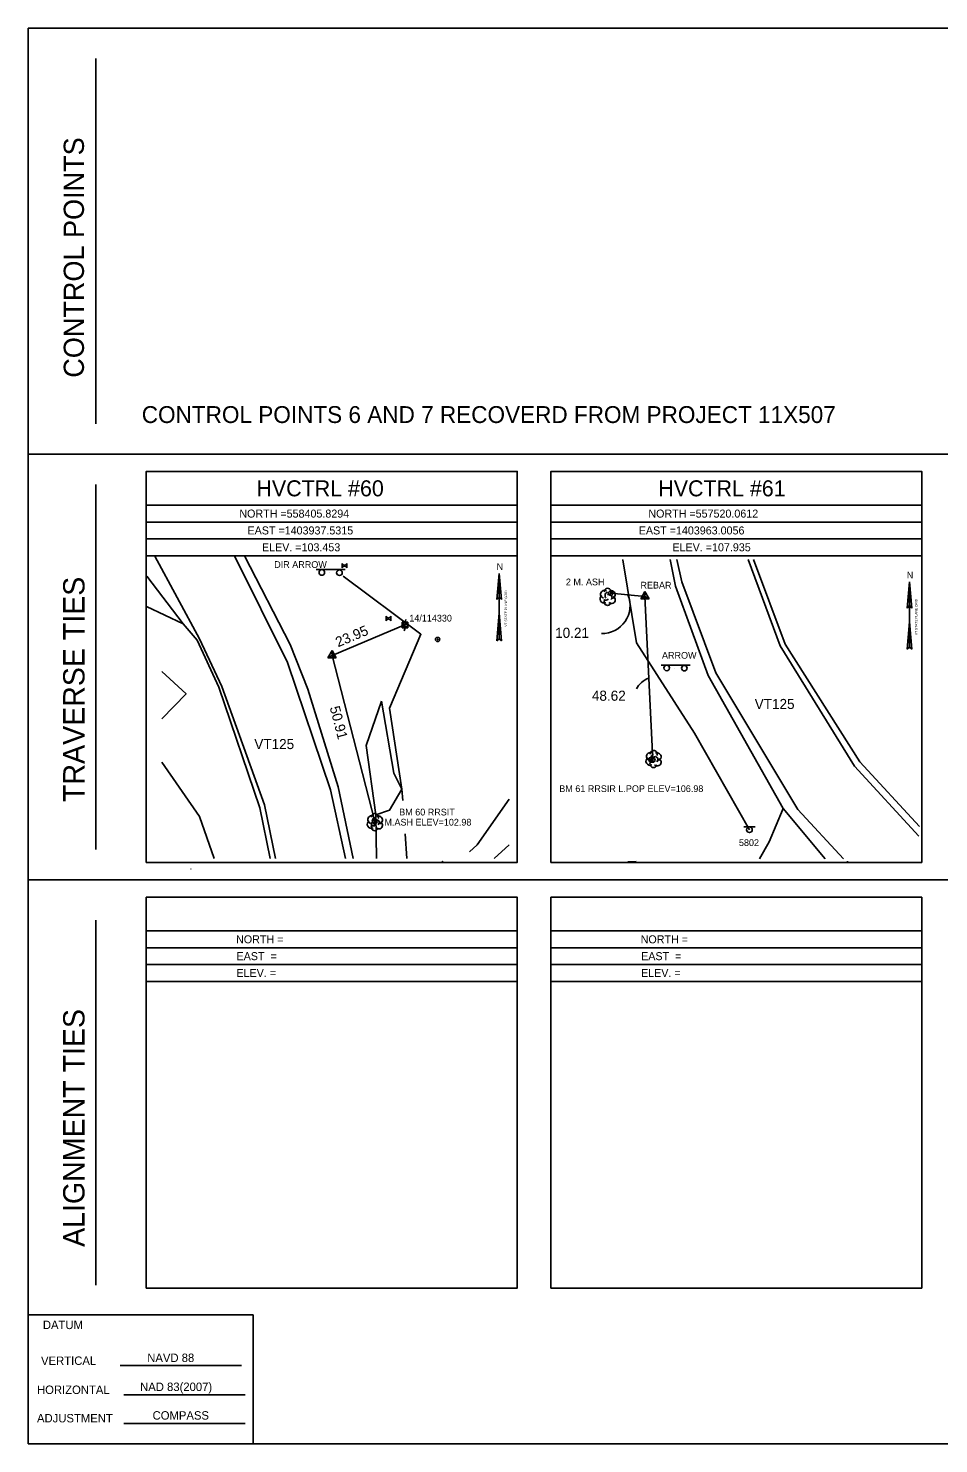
# Model space of a CAD drawing. Extents: x 1514039 to 1514679, y 870735 to 871155.
# Drawn here: x 1514038.6 to 1514308.6, y 870735.2 to 871155.2 of the extents above; entities that cross this region are included whole.
import ezdxf

# ---------------------------------------------------------------- set-up
doc = ezdxf.new("R2010")
doc.units = 0
for name, color, linetype in [('C_A', 7, 'Continuous'), ('C_C', 7, 'Continuous'), ('CBP', 7, 'Continuous'), ('CPBM', 7, 'Continuous'), ('CPSM', 7, 'Continuous'), ('Default', 7, 'Continuous'), ('L_C', 7, 'Continuous'), ('LASF', 7, 'Continuous'), ('LAWA', 7, 'Continuous'), ('LAWE', 7, 'Continuous'), ('LELB', 7, 'Continuous'), ('LSOGT', 7, 'Continuous'), ('LTD', 7, 'Continuous'), ('NBL1', 7, 'Continuous'), ('NBL2', 7, 'Continuous'), ('NNA_P', 7, 'Continuous'), ('PET', 7, 'Continuous'), ('PSP', 7, 'Continuous'), ('R_TIC', 7, 'Continuous'), ('RDG', 7, 'Continuous'), ('RDP', 7, 'Continuous'), ('S_C', 7, 'Continuous'), ('SSGN', 7, 'Continuous'), ('U_C', 7, 'Continuous'), ('UP', 7, 'Continuous'), ('UPGW', 7, 'Continuous'), ('UWV', 7, 'Continuous')]:
    doc.layers.add(name, color=color, linetype=linetype)

msp = doc.modelspace()

# ---------------------------------------------------------------- linework, layer by layer
at = {"layer": 'CBP'}
for centre, radius in [((1514211.27, 870987.54), 0.625), ((1514211.27, 870987.54), 0.0833), ((1514150.45, 870978.27), 0.625), ((1514150.45, 870978.27), 0.0833), ((1514223.82, 870938.08), 0.625), ((1514223.82, 870938.08), 0.0833), ((1514141.37, 870919.82), 0.625), ((1514141.37, 870919.82), 0.0833)]:
    msp.add_circle(centre, radius, dxfattribs=at)
at = {"layer": 'CPBM'}
for p, q in [((1514222.66, 870937.7), (1514222.66, 870938.7)), ((1514222.66, 870938.7), (1514223.66, 870938.7)), ((1514223.66, 870937.7), (1514222.66, 870937.7)), ((1514223.16, 870938.2), (1514223.16, 870938.2)), ((1514223.16, 870938.2), (1514223.16, 870938.2)), ((1514223.66, 870938.7), (1514223.66, 870937.7)), ((1514140.35, 870918.59), (1514140.35, 870919.59)), ((1514140.35, 870919.59), (1514141.35, 870919.59)), ((1514141.35, 870918.59), (1514140.35, 870918.59)), ((1514140.85, 870919.09), (1514140.85, 870919.09)), ((1514140.85, 870919.09), (1514140.85, 870919.09)), ((1514141.35, 870919.59), (1514141.35, 870918.59))]:
    msp.add_line(p, q, dxfattribs=at)
at = {"layer": 'CPSM'}
for p, q in [((1514220.19, 870985.92), (1514221.44, 870988.08)), ((1514222.69, 870985.92), (1514221.44, 870988.08)), ((1514221.44, 870986.64), (1514221.44, 870988.08)), ((1514220.19, 870985.92), (1514221.44, 870986.64)), ((1514220.19, 870985.92), (1514222.69, 870985.92)), ((1514221.44, 870986.64), (1514221.44, 870986.64)), ((1514221.44, 870986.64), (1514222.69, 870985.92)), ((1514127.39, 870968.4), (1514128.64, 870970.56)), ((1514127.39, 870968.4), (1514128.64, 870969.12)), ((1514127.39, 870968.4), (1514129.89, 870968.4)), ((1514129.89, 870968.4), (1514128.64, 870970.56)), ((1514128.64, 870969.12), (1514128.64, 870970.56)), ((1514128.64, 870969.12), (1514128.64, 870969.12)), ((1514128.64, 870969.12), (1514129.89, 870968.4))]:
    msp.add_line(p, q, dxfattribs=at)
at = {"layer": 'Default'}
for points in [[(1514211.37, 870987.57), (1514221.44, 870986.64), (1514223.82, 870938.08)], [(1514150.45, 870978.27), (1514128.64, 870969.12), (1514141.37, 870919.82)]]:
    msp.add_lwpolyline(points, dxfattribs=at)
for centre, radius, start, end in [((1514208.74, 870983.93), 8.3, 268.6041, 22.529), ((1514224.57, 870956.36), 6.31, 107.8692, 153.5783)]:
    msp.add_arc(centre, radius, start, end, dxfattribs=at)
at = {"layer": 'LASF'}
for points in [[(1514143.32, 870955.51), (1514138.75, 870942.45), (1514141.63, 870921.82)], [(1514143.32, 870955.51), (1514146.98, 870934.17), (1514149.38, 870929.42), (1514149.61, 870926.12)], [(1514150.33, 870916.14), (1514150.85, 870908.88)]]:
    msp.add_lwpolyline(points, dxfattribs=at)
at = {"layer": 'LAWA'}
for points in [[(1514252.42, 870917.39), (1514236.11, 870946.04), (1514218.99, 870972.84), (1514214.86, 870997.45), (1514214.84, 870997.56)], [(1514131.92, 870992.64), (1514155.03, 870975.42), (1514145.66, 870953.51), (1514149.38, 870929.42), (1514145.72, 870923.2), (1514141.63, 870921.82), (1514141.86, 870908.88)], [(1514078.16, 870964.37), (1514085.34, 870957.7), (1514078.16, 870950.36)], [(1514078.16, 870937.5), (1514089.32, 870921.35), (1514093.69, 870908.88)]]:
    msp.add_lwpolyline(points, dxfattribs=at)
at = {"layer": 'LAWE'}
msp.add_lwpolyline([(1514181.21, 870926.52), (1514171.74, 870912.92), (1514169.38, 870910.86)], dxfattribs=at)
at = {"layer": 'LELB'}
msp.add_lwpolyline([(1514181.21, 870912.94), (1514176.72, 870908.88)], dxfattribs=at)
at = {"layer": 'LSOGT'}
for p, q in [((1514161.42, 870907.99), (1514161.44, 870908.03)), ((1514161.48, 870907.99), (1514161.42, 870907.99)), ((1514161.44, 870908.03), (1514161.48, 870907.99)), ((1514281.5, 870908.03), (1514281.49, 870908.01)), ((1514281.49, 870908.01), (1514281.53, 870908.01)), ((1514281.56, 870908.01), (1514281.5, 870908.03)), ((1514281.5, 870908.03), (1514281.53, 870908.01)), ((1514281.53, 870908.01), (1514281.5, 870908.03)), ((1514281.53, 870908.01), (1514281.56, 870908.01))]:
    msp.add_line(p, q, dxfattribs=at)
at = {"layer": 'LTD'}
for p, q in [((1514210.37, 870986.57), (1514210.37, 870986.57)), ((1514210.37, 870986.57), (1514210.37, 870986.57)), ((1514223.98, 870938.44), (1514223.98, 870938.44)), ((1514223.98, 870938.44), (1514223.98, 870938.44)), ((1514141.33, 870919.69), (1514141.33, 870919.69)), ((1514141.33, 870919.69), (1514141.33, 870919.69))]:
    msp.add_line(p, q, dxfattribs=at)
for centre in [(1514210.42, 870988), (1514224.03, 870939.87), (1514141.38, 870921.13)]:
    msp.add_arc(centre, 1.05, 335.5272, 180.9563, dxfattribs=at)
for centre, major_axis, ratio, start_param, end_param in [((1514209.58, 870987.24), (1.21, -0.51), 0.895232, 1.570796, 4.712389), ((1514210.16, 870987.03), (-0.208, -0.792), 0.645439, 3.141593, 6.283185), ((1514211.41, 870987.15), (-1.14, -0.48), 0.949671, 1.570796, 4.712389), ((1514209.29, 870985.86), (0.58, -1.04), 0.959034, 3.141593, 6.283185), ((1514210.37, 870985.07), (0.26, 1.06), 0.942809, 1.570796, 4.712389), ((1514209.91, 870985.82), (-0.625, -0.083), 0.423636, 0, 3.141593), ((1514210.87, 870986.4), (-0.5, 0.667), 0.989748, 3.141593, 6.283185), ((1514211.37, 870985.74), (-1.09, 0.79), 0.841452, 1.570796, 4.712389), ((1514222.9, 870937.73), (0.58, -1.04), 0.959034, 3.141593, 6.283185), ((1514223.19, 870939.1), (1.21, -0.51), 0.895232, 1.570796, 4.712389), ((1514223.52, 870937.69), (-0.625, -0.083), 0.423636, 0, 3.141593), ((1514223.77, 870938.9), (-0.208, -0.792), 0.645439, 3.141593, 6.283185), ((1514224.48, 870938.27), (-0.5, 0.667), 0.989748, 3.141593, 6.283185), ((1514224.98, 870937.6), (-1.09, 0.79), 0.841452, 1.570796, 4.712389), ((1514225.02, 870939.02), (-1.14, -0.48), 0.949671, 1.570796, 4.712389), ((1514223.98, 870936.94), (0.26, 1.06), 0.942809, 1.570796, 4.712389), ((1514140.54, 870920.36), (1.21, -0.51), 0.895232, 1.570796, 4.712389), ((1514141.12, 870920.15), (-0.208, -0.792), 0.645439, 3.141593, 6.283185), ((1514141.83, 870919.53), (-0.5, 0.667), 0.989748, 3.141593, 6.283185), ((1514142.37, 870920.28), (-1.14, -0.48), 0.949671, 1.570796, 4.712389), ((1514140.25, 870918.98), (0.58, -1.04), 0.959034, 3.141593, 6.283185), ((1514141.33, 870918.19), (0.26, 1.06), 0.942809, 1.570796, 4.712389), ((1514140.87, 870918.94), (-0.625, -0.083), 0.423636, 0, 3.141593), ((1514142.33, 870918.86), (-1.09, 0.79), 0.841452, 1.570796, 4.712389)]:
    msp.add_ellipse(centre, major_axis=major_axis, ratio=ratio, start_param=start_param, end_param=end_param, dxfattribs=at)
at = {"layer": 'NBL1'}
msp.add_lwpolyline([(1514038.57, 870735.22), (1514678.57, 870735.22), (1514678.57, 871155.22), (1514038.57, 871155.22)], close=True, dxfattribs=at)
at = {"layer": 'NBL2'}
for p, q in [((1514058.57, 871037.89), (1514058.57, 871146.22)), ((1514038.57, 871028.89), (1514678.57, 871028.89)), ((1514058.57, 870911.55), (1514058.57, 871019.89)), ((1514183.57, 871013.72), (1514073.57, 871013.72)), ((1514303.57, 871013.72), (1514193.57, 871013.72)), ((1514183.57, 871008.72), (1514073.57, 871008.72)), ((1514303.57, 871008.72), (1514193.57, 871008.72)), ((1514183.57, 871003.72), (1514073.57, 871003.72)), ((1514303.57, 871003.72), (1514193.57, 871003.72)), ((1514183.57, 870998.72), (1514073.57, 870998.72)), ((1514197.6, 870998.72), (1514193.57, 870998.72)), ((1514300.42, 870998.72), (1514197.6, 870998.72)), ((1514303.57, 870998.72), (1514300.42, 870998.72)), ((1514038.57, 870902.55), (1514678.57, 870902.55)), ((1514058.57, 870782.22), (1514058.57, 870890.55)), ((1514183.57, 870887.39), (1514073.57, 870887.39)), ((1514303.57, 870887.39), (1514193.57, 870887.39)), ((1514183.57, 870882.39), (1514073.57, 870882.39)), ((1514303.57, 870882.39), (1514193.57, 870882.39)), ((1514183.57, 870877.39), (1514073.57, 870877.39)), ((1514303.57, 870877.39), (1514193.57, 870877.39)), ((1514183.57, 870872.39), (1514073.57, 870872.39)), ((1514303.57, 870872.39), (1514193.57, 870872.39)), ((1514105.24, 870773.47), (1514038.57, 870773.47)), ((1514105.24, 870773.47), (1514105.24, 870735.22)), ((1514105.24, 870773.47), (1514105.24, 870735.22)), ((1514065.81, 870758.45), (1514101.81, 870758.42)), ((1514066.92, 870749.67), (1514102.92, 870749.67)), ((1514066.92, 870741.24), (1514102.92, 870741.21))]:
    msp.add_line(p, q, dxfattribs=at)
for points in [[(1514073.57, 870907.72), (1514183.57, 870907.72), (1514183.57, 871023.72), (1514073.57, 871023.72)], [(1514193.57, 870907.72), (1514303.57, 870907.72), (1514303.57, 871023.72), (1514193.57, 871023.72)], [(1514073.57, 870781.39), (1514183.57, 870781.39), (1514183.57, 870897.39), (1514073.57, 870897.39)], [(1514193.57, 870781.39), (1514303.57, 870781.39), (1514303.57, 870897.39), (1514193.57, 870897.39)]]:
    msp.add_lwpolyline(points, close=True, dxfattribs=at)
at = {"layer": 'NNA_P'}
for p, q in [((1514177.55, 870985.68), (1514178.24, 870993.47)), ((1514178.24, 870974.1), (1514178.24, 870993.47)), ((1514178.93, 870985.68), (1514178.24, 870993.47)), ((1514299.21, 870983.17), (1514299.9, 870990.96)), ((1514299.91, 870971.59), (1514299.9, 870990.96)), ((1514300.6, 870983.17), (1514299.9, 870990.96)), ((1514177.55, 870985.68), (1514178.24, 870986.45)), ((1514178.94, 870985.68), (1514178.24, 870986.45)), ((1514299.21, 870983.17), (1514299.91, 870983.94)), ((1514300.6, 870983.17), (1514299.91, 870983.94)), ((1514178.24, 870981.62), (1514177.52, 870973.46)), ((1514178.24, 870981.62), (1514178.96, 870973.46)), ((1514299.91, 870979.11), (1514299.19, 870970.95)), ((1514299.91, 870979.11), (1514300.63, 870970.95)), ((1514178.24, 870974.1), (1514177.52, 870973.46)), ((1514178.24, 870974.1), (1514178.96, 870973.46)), ((1514299.91, 870971.59), (1514299.19, 870970.95)), ((1514299.91, 870971.59), (1514300.63, 870970.95))]:
    msp.add_line(p, q, dxfattribs=at)
at = {"layer": 'PET'}
for points in [[(1514076.06, 870998.57), (1514089.38, 870974.05), (1514095.97, 870959.95), (1514108.6, 870924.8), (1514111.87, 870908.88)], [(1514099.72, 870998.72), (1514115.49, 870967.06), (1514128.24, 870929.25), (1514132.63, 870908.88)], [(1514230.91, 870997.56), (1514232.35, 870990.97), (1514242.45, 870963.92), (1514266.76, 870923.37), (1514280.36, 870908.77)], [(1514252.07, 870997.56), (1514261.57, 870971.96), (1514283.59, 870936.3), (1514302.72, 870915.5)]]:
    msp.add_lwpolyline(points, dxfattribs=at)
at = {"layer": 'PSP'}
for points in [[(1514102.7, 870998.72), (1514116.25, 870972.41), (1514121.44, 870959.1), (1514130.46, 870930.18), (1514134.89, 870908.88)], [(1514228.89, 870997.56), (1514230.48, 870989.66), (1514240.22, 870963.21), (1514262.46, 870923.69), (1514274.86, 870908.77)], [(1514253.68, 870997.56), (1514263.06, 870972.49), (1514285.19, 870937.51), (1514302.88, 870918.36)], [(1514073.73, 870992.68), (1514084.52, 870978.46), (1514088.66, 870973.66), (1514095.12, 870959.7), (1514107.2, 870923.95), (1514110.26, 870908.88)]]:
    msp.add_lwpolyline(points, dxfattribs=at)
at = {"layer": 'R_TIC'}
msp.add_lwpolyline([(1514086.81, 870905.74), (1514086.75, 870905.81)], dxfattribs=at)
at = {"layer": 'RDG'}
for points in [[(1514073.64, 870983.69), (1514084.52, 870978.46)], [(1514262.46, 870923.69), (1514258.34, 870913.83), (1514255.43, 870908.77)]]:
    msp.add_lwpolyline(points, dxfattribs=at)
at = {"layer": 'RDP'}
msp.add_lwpolyline([(1514218.83, 870907.98), (1514216.42, 870907.85)], dxfattribs=at)
at = {"layer": 'SSGN'}
for p, q in [((1514123.97, 870994.58), (1514132.57, 870994.58)), ((1514127.99, 870993.68), (1514127.99, 870993.68)), ((1514226.26, 870966.26), (1514234.86, 870966.26)), ((1514230.28, 870965.35), (1514230.28, 870965.35)), ((1514250.79, 870918.24), (1514254.13, 870918.24)), ((1514252.44, 870917.41), (1514252.44, 870917.41))]:
    msp.add_line(p, q, dxfattribs=at)
for centre in [(1514125.63, 870993.75), (1514130.85, 870993.68), (1514227.92, 870965.42), (1514233.14, 870965.35), (1514252.44, 870917.41)]:
    msp.add_circle(centre, 0.833, dxfattribs=at)
at = {"layer": 'UP'}
for p, q in [((1514150.58, 870979.79), (1514150.33, 870978.96)), ((1514149.49, 870977.29), (1514149.49, 870978.96)), ((1514149.49, 870978.96), (1514151.16, 870978.96)), ((1514151.16, 870977.29), (1514149.49, 870977.29)), ((1514150.08, 870976.46), (1514150.33, 870977.29)), ((1514150.33, 870978.13), (1514150.33, 870978.13)), ((1514151.16, 870978.96), (1514151.16, 870977.29))]:
    msp.add_line(p, q, dxfattribs=at)
msp.add_circle((1514150.33, 870978.13), 0.833, dxfattribs=at)
at = {"layer": 'UPGW'}
for radius in [0.625, 0.0833]:
    msp.add_circle((1514159.96, 870973.86), radius, dxfattribs=at)
at = {"layer": 'UWV'}
for p, q in [((1514131.69, 870996.44), (1514133.03, 870995.11)), ((1514133.03, 870996.44), (1514131.69, 870995.11)), ((1514144.75, 870980.76), (1514145.3, 870980.21)), ((1514145.3, 870979.97), (1514144.75, 870979.42)), ((1514146.09, 870980.76), (1514145.54, 870980.21)), ((1514145.54, 870979.97), (1514146.09, 870979.42))]:
    msp.add_line(p, q, dxfattribs=at)
for points in [[(1514131.69, 870996.44), (1514131.69, 870995.11)], [(1514133.03, 870995.11), (1514133.03, 870996.44)], [(1514144.75, 870980.76), (1514144.75, 870979.42)], [(1514146.09, 870979.42), (1514146.09, 870980.76)]]:
    msp.add_lwpolyline(points, dxfattribs=at)
msp.add_lwpolyline([(1514145.66, 870980.09), (1514145.42, 870980.33), (1514145.18, 870980.09), (1514145.42, 870979.86)], close=True, dxfattribs=at)
msp.add_circle((1514132.36, 870995.77), 0.167, dxfattribs=at)

# ---------------------------------------------------------------- texts
at = {"layer": 'C_A'}
msp.add_text('REBAR', height=2, dxfattribs=at).set_placement((1514220.12, 870988.98))
at = {"layer": 'C_C'}
for s, p in [('BM 61 RRSIR L.POP ELEV=106.98', (1514196.04, 870928.59)), (' M.ASH ELEV=102.98', (1514143.45, 870918.64)), ('BM 60 RRSIT', (1514148.57, 870921.64))]:
    msp.add_text(s, height=2, dxfattribs=at).set_placement(p)
at = {"layer": 'Default'}
for s, height, p in [('CONTROL POINTS 6 AND 7 RECOVERD FROM PROJECT 11X507', 5, (1514072.22, 871038.1)), ('10.21', 3, (1514194.82, 870974.34)), ('48.62', 3, (1514205.72, 870955.68)), ('VT125', 3, (1514254.01, 870953.22)), ('VT125', 3, (1514105.6, 870941.33))]:
    msp.add_text(s, height=height, dxfattribs=at).set_placement(p)
for s, rotation, p in [('23.95', 22.7603, (1514130.45, 870971.53)), ('50.91', 284.4772, (1514127.95, 870953.68))]:
    msp.add_text(s, height=3, rotation=rotation, dxfattribs=at).set_placement(p)
at = {"layer": 'L_C'}
msp.add_text('2 M. ASH', height=2, dxfattribs=at).set_placement((1514198.01, 870989.94))
at = {"layer": 'NBL2'}
for s, height, rotation, p in [('CONTROL POINTS', 6, 90, (1514055.07, 871051.54)), ('TRAVERSE TIES', 6.3332, 90, (1514055.24, 870925.65)), ('ALIGNMENT TIES', 6.3332, 90, (1514055.24, 870793.62)), ('VERTICAL', 2.5, 0.1439, (1514042.35, 870758.57))]:
    msp.add_text(s, height=height, rotation=rotation, dxfattribs=at).set_placement(p)
for s, height, p in [('HVCTRL #60', 4.75, (1514106.23, 871016.34)), ('HVCTRL #61', 4.75, (1514225.41, 871016.34)), ('NORTH =558405.8294', 2.375, (1514101.16, 871010.03)), ('NORTH =557520.0612', 2.375, (1514222.47, 871010.03)), ('EAST =1403937.5315', 2.375, (1514103.58, 871005.03)), ('EAST =1403963.0056', 2.375, (1514219.62, 871005.03)), ('ELEV. =103.453', 2.375, (1514107.87, 871000.03)), ('ELEV. =107.935', 2.375, (1514229.61, 871000.03)), ('NORTH =             ', 2.375, (1514100.19, 870883.7)), ('NORTH =             ', 2.375, (1514220.19, 870883.7)), ('EAST  =             ', 2.375, (1514100.33, 870878.7)), ('EAST  =             ', 2.375, (1514220.33, 870878.7)), ('ELEV. =             ', 2.375, (1514100.3, 870873.7)), ('ELEV. =             ', 2.375, (1514220.3, 870873.7)), ('DATUM', 2.5, (1514042.89, 870769.23)), (' NAVD 88  ', 2.5, (1514072.92, 870759.46)), ('HORIZONTAL', 2.5, (1514041.15, 870749.97)), ('NAD 83(2007)', 2.5, (1514071.73, 870750.85)), ('ADJUSTMENT', 2.5, (1514041.15, 870741.54)), ('  COMPASS ', 2.5, (1514073.57, 870742.36))]:
    msp.add_text(s, height=height, dxfattribs=at).set_placement(p)
at = {"layer": 'NNA_P'}
for p in [(1514177.48, 870994.49), (1514299.14, 870991.97)]:
    msp.add_text('N', height=1.97, dxfattribs=at).set_placement(p)
for p in [(1514180.59, 870977.66), (1514302.26, 870975.15)]:
    msp.add_text('VT STATE PLANE GRID', height=0.7, rotation=90.0204, dxfattribs=at).set_placement(p)
at = {"layer": 'S_C'}
for s, p in [('DIR ARROW', (1514111.5, 870995.1)), ('ARROW', (1514226.51, 870968.16)), ('5802', (1514249.33, 870912.57))]:
    msp.add_text(s, height=2, dxfattribs=at).set_placement(p)
at = {"layer": 'U_C'}
msp.add_text('14/114330', height=2, dxfattribs=at).set_placement((1514151.56, 870979.18))

doc.saveas('drawing.dxf')
